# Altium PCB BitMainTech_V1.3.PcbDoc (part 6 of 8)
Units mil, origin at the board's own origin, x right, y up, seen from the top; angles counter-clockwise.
Board outline 9842.52 x 6082.68 mil, 4 copper layers (Top Layer, Mid-Layer 1, Mid-Layer 2, Bottom Layer); 987 components, 282 nets, 3694 pads, 3174 vias.
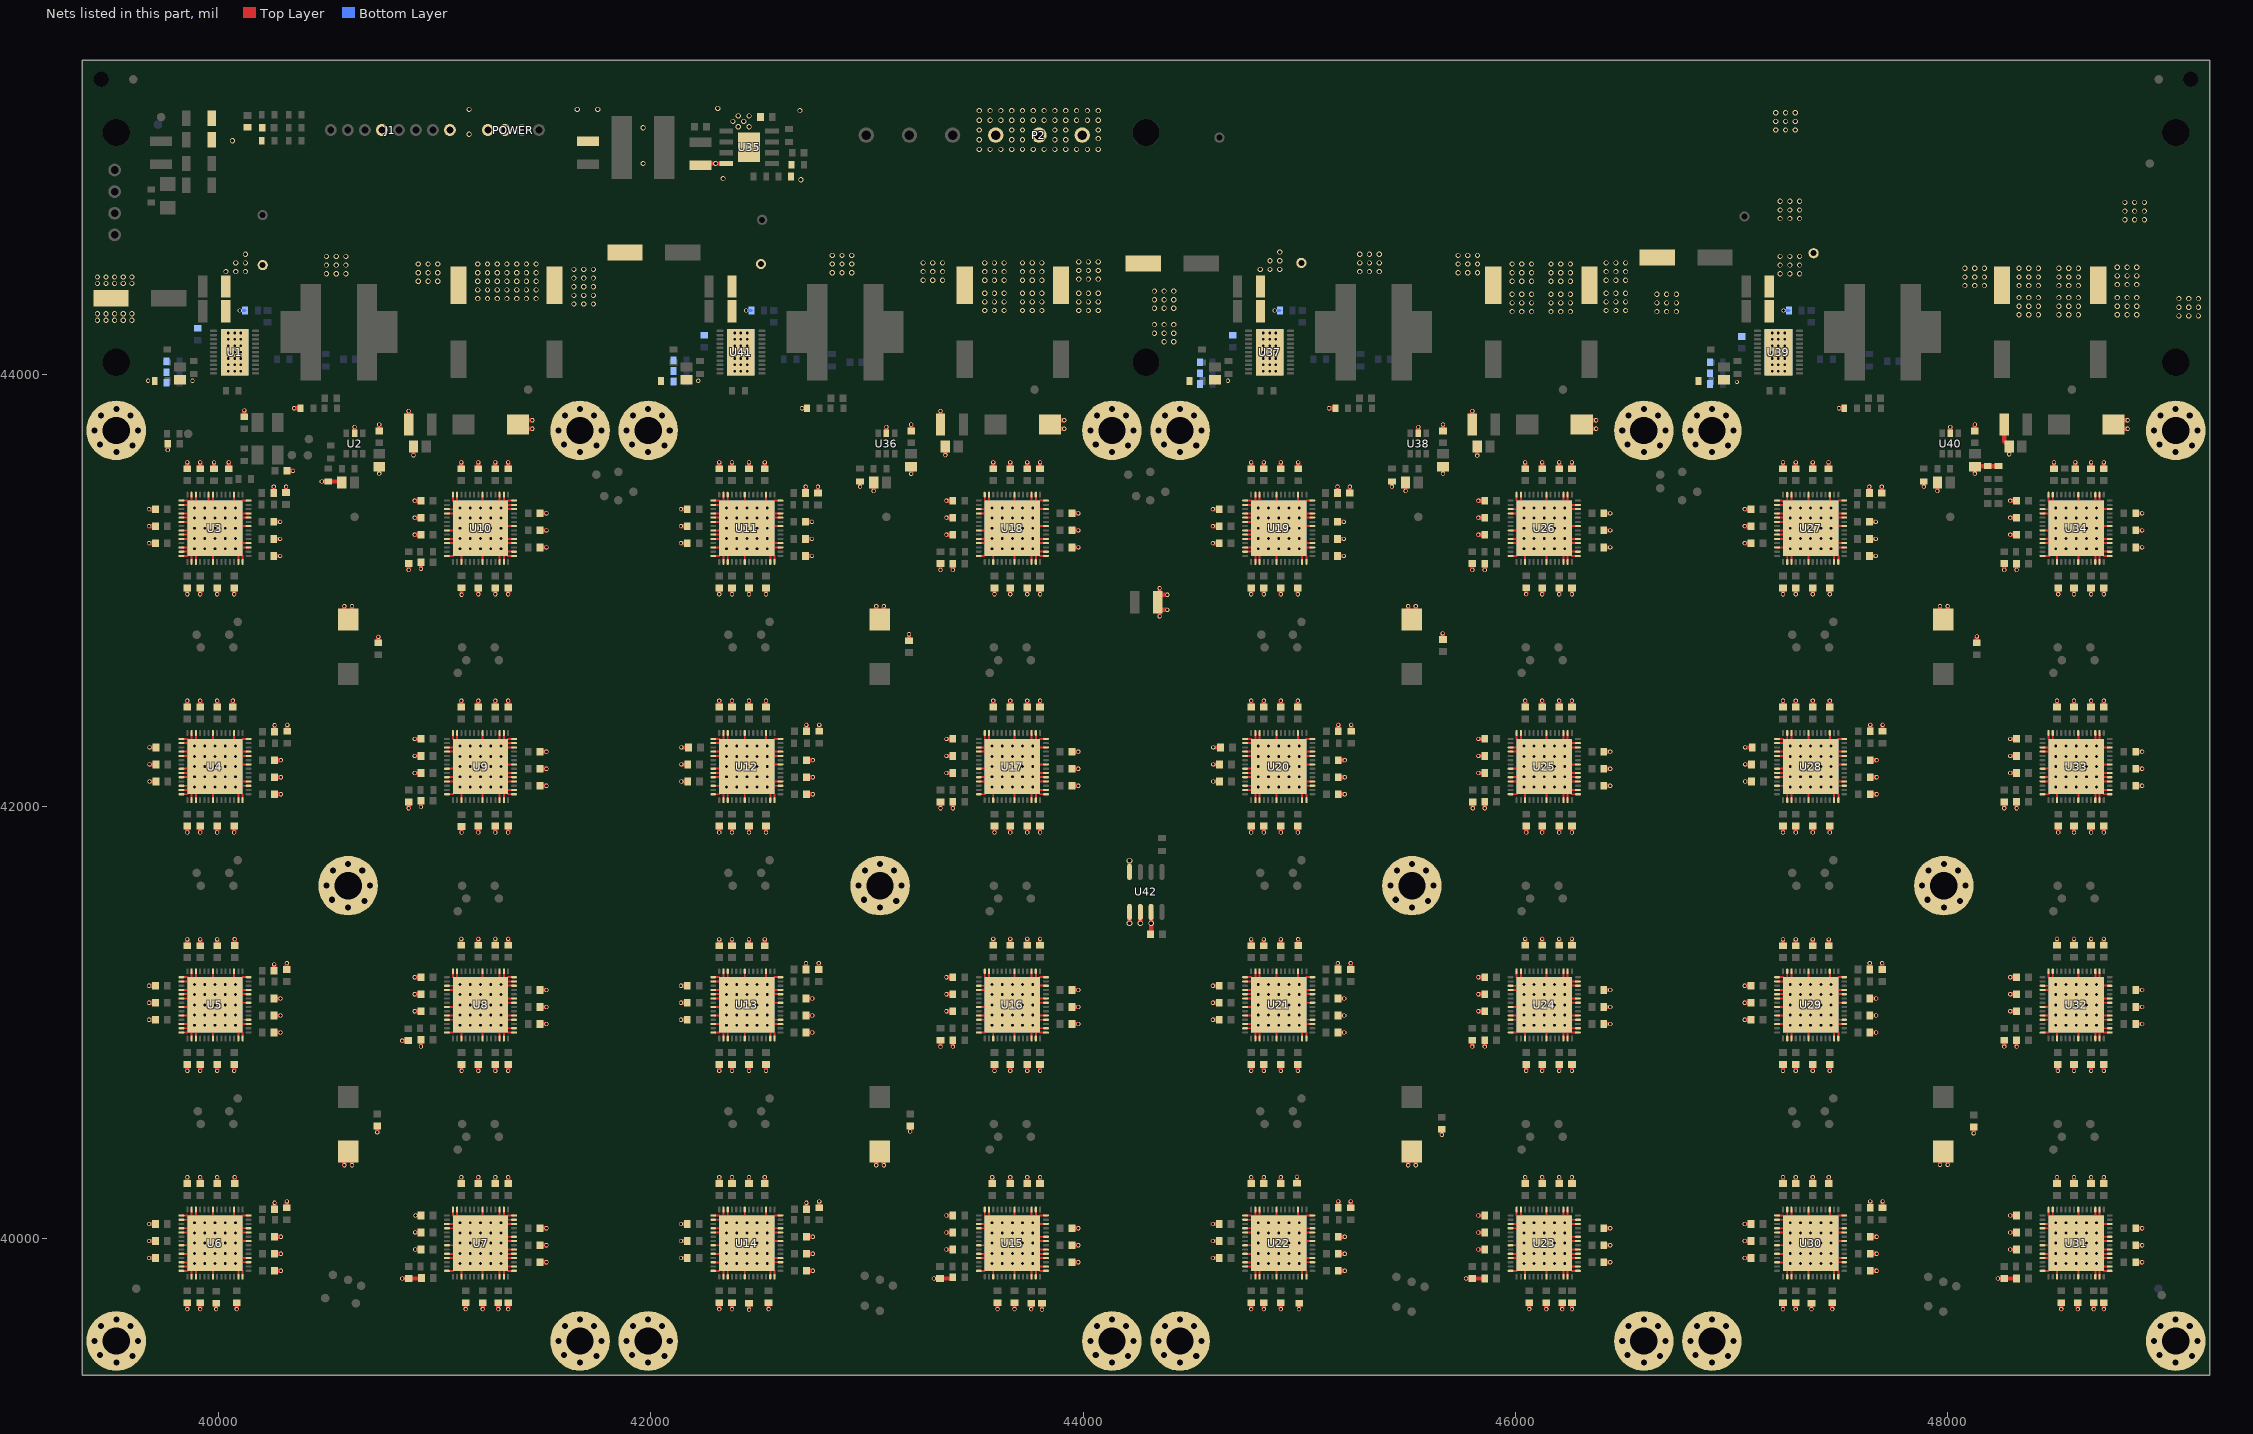
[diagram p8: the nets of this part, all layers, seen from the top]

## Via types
v1: diameter 19, hole 12, Top Layer to Bottom Layer, 1347 vias
v2: diameter 25.98, hole 12.99, Top Layer to Bottom Layer, 800 vias
v3: diameter 24, hole 16, Top Layer to Bottom Layer, 778 vias
v4: diameter 50, hole 28, Top Layer to Bottom Layer, 160 vias
v5: diameter 19.68, hole 11.81, Top Layer to Bottom Layer, 84 vias
v6: diameter 26, hole 18, Top Layer to Bottom Layer, 5 vias

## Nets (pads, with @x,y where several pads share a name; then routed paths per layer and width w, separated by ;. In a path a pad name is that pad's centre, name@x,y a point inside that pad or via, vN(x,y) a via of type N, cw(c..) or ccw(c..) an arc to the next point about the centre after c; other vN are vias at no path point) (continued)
GND: (continued)
  Top Layer w20: v1(39679.13,39911.42) C57.1@39708.66,39911.42 ; v1(39679.13,39990.16) C59.1@39708.66,39990.16 ; v1(39679.13,40068.9) C58.1@39708.66,40068.9 ; v1(39679.13,41013.78) C130.1@39708.66,41013.78 ; v1(39679.13,41092.52) C131.1@39708.66,41092.52 ; v1(39679.13,41171.26) C134.1@39708.66,41171.26 ; v1(39679.13,43218.5) C132.1@39708.66,43218.5 ; v1(39679.13,43297.24) C122.1@39708.66,43297.24 ; v1(39679.13,43375.98) C45.1@39708.66,43375.98 ; v1(39681.1,42116.14) C115.1@39710.63,42116.14 ; v1(39681.1,42194.88) C114.1@39710.63,42194.88 ; v1(39681.1,42273.62) C113.1@39710.63,42273.62 ; v1(39765.75,43649.61) C31.2@39765.75,43679.13 ; v1(39856.3,39675.2) C104.1@39856.3,39704.72 ; C103.1@39856.3,40255.91 v1(39856.3,40285.43) ; v1(39856.3,40777.56) C43.1@39856.3,40807.09 ; C35.1@39856.3,41356.3 v1(39856.3,41385.83) ; v1(39856.3,41879.92) C41.1@39856.3,41909.45 ; C33.1@39856.3,42460.63 v1(39856.3,42490.16) ; v1(39856.3,42982.28) C99.1@39856.3,43011.81 ; C106.1@39856.3,43562.99 v1(39856.3,43592.52) ; v1(39915.35,39675.2) C53.1@39915.35,39704.72 ; C124.1@39915.35,40255.91 v1(39915.35,40285.43) ; v1(39915.35,40777.56) C121.1@39915.35,40807.09 ; C52.1@39915.35,41356.3 v1(39915.35,41385.83) ; v1(39915.35,41879.92) C116.1@39915.35,41909.45 ; C110.1@39915.35,42460.63 v1(39915.35,42490.16) ; v1(39915.35,42982.28) C56.1@39915.35,43011.81 ; C47.1@39915.35,43562.99 v1(39915.35,43592.52) ; C50.1@39980,43562.56 v1(39980,43592.09) ; v1(39989.25,39675) C54.1@39989.25,39702.44 ; C125.1@39994.09,40255.91 v1(39994.09,40285.43) ; v1(39994.09,40777.56) C126.1@39994.09,40807.09 ; C51.1@39994.09,41356.3 v1(39994.09,41385.83) ; v1(39994.09,41879.92) C117.1@39994.09,41909.45 ; C111.1@39994.09,42460.63 v1(39994.09,42490.16) ; v1(39994.09,42982.28) C63.1@39994.09,43011.81 ; C133.1@40047.24,43562.99 v1(40047.24,43592.52) ; C112.1@40066.93,42460.63 v1(40066.93,42490.16) ; v1(40072.83,40777.56) C127.1@40072.83,40807.09 ; v1(40072.83,41879.92) C118.1@40072.83,41909.45 ; v1(40072.83,42982.28) C108.1@40072.83,43011.81 ; C123.1@40075,40255.9 v1(40075,40285.43) ; C48.1@40075,41357.56 v1(40075,41387.09) ; v1(40084.65,39675.2) C55.1@40084.65,39704.72 ; C30.2@40120.08,43803.15 v1(40120.08,43832.68) ; C105.1@40255.91,43159.45 v1(40285.43,43159.45) ; C49.1@40255.91,43238.19 v1(40285.43,43238.19) ; C109.1@40255.91,43316.93 v1(40285.43,43316.93) ; C22.1@40255.91,43450.79 v1(40255.91,43480.31) ; C40.1@40257.87,40954.72 v1(40287.4,40954.72) ; C128.1@40257.87,41033.46 v1(40287.4,41033.46) ; C129.1@40257.87,41112.2 v1(40287.4,41112.2) ; C26.1@40257.87,41240.16 v1(40257.87,41269.68) ; C107.1@40259.84,39852.36 v1(40289.37,39852.36) ; C135.1@40259.84,39931.1 v1(40289.37,39931.1) ; C136.1@40259.84,40009.84 v1(40289.37,40009.84) ; C28.1@40259.84,40137.8 v1(40259.84,40167.32) ; C39.1@40259.84,42057.09 v1(40289.37,42057.09) ; C119.1@40259.84,42135.83 v1(40289.37,42135.83) ; C120.1@40259.84,42214.57 v1(40289.37,42214.57) ; C24.1@40259.84,42346.46 v1(40259.84,42375.98) ; C21.2@40312.99,43452.76 v1(40312.99,43480) ; C27.2@40316.93,40143.7 v1(40316.93,40173.23) ; C92.2@40316.93,41246.06 v1(40316.93,41275.59) ; C29.2@40316.93,43553.15 v1(40345,43553.15) ; C90.2@40318.9,42348.43 v1(40318.9,42377.95) ; v1(40350.39,43842.52) R12.2@40379.92,43842.52 ; v1(40478.35,43503.94) R14.1@40507.87,43503.94 C16.1@40570.87,43503.94 ; v1(40582.68,40340.55) C18.2@40582.68,40405.51 ; C17.2@40582.68,42866.14 v1(40582.68,42927.17) ; v1(40618.11,40340.55) C18.2@40618.11,40401.57 ; C17.2@40618.11,42862.2 v1(40618.11,42927.17) ; U2.2@40629.92,43726.38 v1(40629.92,43755.91) ; v1(40735,40492.91) C19.1@40735,40522.44 ; C20.1@40740,42757.56 v1(40740,42785.12) ; v1(40744.09,43540) C15.1@40744.09,43572.83 ; C14.1@40744.09,43738.19 v1(40744.09,43767.72) ; v1(40850,40917.32) C25.2@40877.95,40917.32 ; v1(40850.39,39816.93) C94.2@40879.92,39816.93 C89.1@40938.98,39816.93 ; v1(40879.92,41992.13) C23.2@40879.92,42021.65 ; v1(40879.92,43094.49) C88.2@40879.92,43124.02 ; C8.1@40879.92,43767.72 v1(40879.92,43830) ; v1(40902.47,43625) C9.1@40902.47,43666 ; v1(40907.48,41053.15) C46.1@40937.01,41053.15 ; v1(40907.48,41131.89) C87.1@40937.01,41131.89 ; v1(40907.48,41210.63) C34.1@40937.01,41210.63 ; v1(40907.48,42155.51) C85.1@40937.01,42155.51 ; v1(40907.48,42234.25) C86.1@40937.01,42234.25 ; v1(40907.48,42312.99) C38.1@40937.01,42312.99 ; v1(40907.48,43257.87) C84.1@40937.01,43257.87 ; v1(40907.48,43336.61) C83.1@40937.01,43336.61 ; v1(40907.48,43415.35) C98.1@40937.01,43415.35 ; v1(40910,39950.79) C147.1@40937.01,39950.79 ; v1@40910.47,40029.53 C146.1@40937.01,40029.53 ; v1(40911.73,40108.27) C32.1@40937.01,40108.27 ; v1(40937.01,40890) C91.1@40937.01,40921.26 ; v1(40937.01,41998.03) C93.1@40937.01,42027.56 ; v1(40937.01,43100.39) C95.1@40937.01,43129.92 ; C142.1@41124.02,40255.91 v1(41124.02,40285.43) ; C62.1@41124.02,41358.27 v1(41124.02,41387.8) ; C69.1@41124.02,42460.63 v1(41124.02,42490.16) ; C82.1@41124.02,43562.99 v1(41124.02,43592.52) ; v1(41125,40777.91) C148.1@41125,40807.44 ; v1(41125,41880) C64.1@41125,41909.53 ; v1(41125,42980) C73.1@41125,43009.53 ; v1(41143.7,39675.2) C137.1@41143.7,39704.72 ; C141.1@41202.76,40255.91 v1(41202.76,40285.43) ; v1(41202.76,40777.56) C149.1@41202.76,40807.09 ; C61.1@41202.76,41358.27 v1(41202.76,41387.8) ; v1(41202.76,41879.92) C65.1@41202.76,41909.45 ; C68.1@41202.76,42460.63 v1(41202.76,42490.16) ; v1(41202.76,42982.28) C74.1@41202.76,43011.81 ; C81.1@41202.76,43562.99 v1(41202.76,43592.52) ; v1(41222.44,39675.2) C138.1@41222.44,39704.72 ; C140.1@41281.5,40255.91 v1(41281.5,40285.43) ; v1(41281.5,40777.56) C150.1@41281.5,40807.09 ; C60.1@41281.5,41358.27 v1(41281.5,41387.8) ; v1(41281.5,41879.92) C66.1@41281.5,41909.45 ; C67.1@41281.5,42460.63 v1(41281.5,42490.16) ; v1(41281.5,42982.28) C76.1@41281.5,43011.81 ; C80.1@41281.5,43562.99 v1(41281.5,43592.52) ; v1(41295.28,39675.2) C139.1@41295.28,39704.72 ; v1(41340.55,39675.2) C36.1@41340.55,39704.72 ; C102.1@41340.55,40255.91 v1(41340.55,40285.43) ; v1(41340.55,40777.56) C37.1@41340.55,40807.09 ; C101.1@41340.55,41358.27 v1(41340.55,41387.8) ; v1(41340.55,41879.92) C96.1@41340.55,41909.45 ; C100.1@41340.55,42460.63 v1(41340.55,42490.16) ; v1(41340.55,42982.28) C97.1@41340.55,43011.81 ; C42.1@41340.55,43562.99 v1(41340.55,43592.52) ; C4.2@41381.89,43748.03 v1(41452.76,43748.03) ; C4.2@41385.83,43787.4 v1(41452.76,43787.4) ; C145.1@41488.19,39891.73 v1(41517.72,39891.73) ; C144.1@41488.19,39970.47 v1(41517.72,39970.47) ; C143.1@41488.19,40049.21 v1(41517.72,40049.21) ; C151.1@41488.19,40994.09 v1(41517.72,40994.09) ; C75.1@41488.19,41072.83 v1(41517.72,41072.83) ; C44.1@41488.19,41151.57 v1(41517.72,41151.57) ; C70.1@41488.19,42096.46 v1(41517.72,42096.46) ; C71.1@41488.19,42175.2 v1(41517.72,42175.2) ; C72.1@41488.19,42253.94 v1(41517.72,42253.94) ; C77.1@41488.19,43198.82 v1(41517.72,43198.82) ; C78.1@41488.19,43277.56 v1(41517.72,43277.56) ; C79.1@41488.19,43356.3 v1(41517.72,43356.3) ; v1(42139.76,39911.42) C189.1@42169.29,39911.42 ; v1(42139.76,39990.16) C191.1@42169.29,39990.16 ; v1(42139.76,40068.9) C190.1@42169.29,40068.9 ; v1(42139.76,41013.78) C262.1@42169.29,41013.78 ; v1(42139.76,41092.52) C263.1@42169.29,41092.52 ; v1(42139.76,41171.26) C266.1@42169.29,41171.26 ; v1(42139.76,43218.5) C264.1@42169.29,43218.5 ; v1(42139.76,43297.24) C254.1@42169.29,43297.24 ; v1(42139.76,43375.98) C177.1@42169.29,43375.98 ; v1(42141.73,42116.14) C247.1@42171.26,42116.14 ; v1(42141.73,42194.88) C246.1@42171.26,42194.88 ; v1(42141.73,42273.62) C245.1@42171.26,42273.62 ; C548.1@42242.09,44975 U35.4@42348.7,44975 ; v1(42316.93,39675.2) C236.1@42316.93,39704.72 ; C235.1@42316.93,40255.91 v1(42316.93,40285.43) ; v1(42316.93,40777.56) C175.1@42316.93,40807.09 ; C167.1@42316.93,41356.3 v1(42316.93,41385.83) ; v1(42316.93,41879.92) C173.1@42316.93,41909.45 ; C165.1@42316.93,42460.63 v1(42316.93,42490.16) ; v1(42316.93,42982.28) C231.1@42316.93,43011.81 ; C238.1@42316.93,43562.99 v1(42316.93,43592.52) ; v1(42375.98,39675.2) C185.1@42375.98,39704.72 ; C256.1@42375.98,40255.91 v1(42375.98,40285.43) ; v1(42375.98,40777.56) C253.1@42375.98,40807.09 ; C184.1@42375.98,41356.3 v1(42375.98,41385.83) ; v1(42375.98,41879.92) C248.1@42375.98,41909.45 ; C242.1@42375.98,42460.63 v1(42375.98,42490.16) ; v1(42375.98,42982.28) C188.1@42375.98,43011.81 ; C179.1@42375.98,43562.99 v1(42375.98,43592.52) ; C257.1@42454.72,40255.91 v1(42454.72,40285.43) ; v1(42454.72,40777.56) C258.1@42454.72,40807.09 ; C183.1@42454.72,41356.3 v1(42454.72,41385.83) ; v1(42454.72,41879.92) C249.1@42454.72,41909.45 ; C243.1@42454.72,42460.63 v1(42454.72,42490.16) ; v1(42454.72,42982.28) C195.1@42454.72,43011.81 ; C182.1@42454.72,43562.99 v1(42454.72,43592.52) ; v1(42455,39672.91) C186.1@42455,39702.44 ; C255.1@42527.56,40255.91 v1(42527.56,40285.43) ; C180.1@42527.56,41356.3 v1(42527.56,41385.83) ; C265.1@42527.56,43562.99 v1(42527.56,43592.52) ; v1(42533.46,40777.56) C259.1@42533.46,40807.09 ; v1(42533.46,41879.92) C250.1@42533.46,41909.45 ; C244.1@42533.46,42460.63 v1(42533.46,42490.16) ; v1(42533.46,42982.28) C240.1@42533.46,43011.81 ; v1(42545.28,39675.2) C187.1@42545.28,39704.72 ; v1(42700,43842.52) R33.2@42722.44,43842.52 ; C237.1@42716.54,43159.45 v1(42746.06,43159.45) ; C181.1@42716.54,43238.19 v1(42746.06,43238.19) ; C241.1@42716.54,43316.93 v1(42746.06,43316.93) ; C157.1@42716.54,43450.79 v1(42716.54,43480.31) ; C172.1@42718.5,40954.72 v1(42748.03,40954.72) ; C260.1@42718.5,41033.46 v1(42748.03,41033.46) ; C261.1@42718.5,41112.2 v1(42748.03,41112.2) ; C161.1@42718.5,41246.06 v1(42718.5,41275.59) ; C239.1@42720.47,39852.36 v1(42750,39852.36) ; C267.1@42720.47,39931.1 v1(42750,39931.1) ; C268.1@42720.47,40009.84 v1(42750,40009.84) ; C163.1@42720.47,40137.8 v1(42720.47,40167.32) ; C171.1@42720.47,42057.09 v1(42750,42057.09) ; C251.1@42720.47,42135.83 v1(42750,42135.83) ; C252.1@42720.47,42214.57 v1(42750,42214.57) ; C159.1@42720.47,42348.43 v1(42720.47,42377.95) ; C156.2@42773.62,43450.79 v1(42773.62,43480.32) ; C224.2@42777.56,41246.06 v1(42777.56,41275.59) ; C162.2@42779.53,40143.7 v1(42779.53,40173.23) ; C222.2@42779.53,42348.43 v1(42779.53,42377.95) ; v1(42968.5,43480) R35.1@42968.5,43503.94 ; v1(43031.5,43460) C563.1@43031.5,43500 ; v1(43043.31,40340.55) C153.2@43043.31,40405.51 ; C152.2@43043.31,42866.14 v1(43043.31,42927.17) ; v1(43078.74,40340.55) C153.2@43078.74,40401.57 ; C152.2@43078.74,42862.2 v1(43078.74,42927.17) ; U36.2@43090.55,43726.38 v1(43090.55,43755.91) ; C155.1@43195,42767.56 v1(43195,42797.09) ; v1(43200,40496.85) C154.1@43200,40522.44 ; v1(43204.72,43539.37) C562.1@43204.72,43572.83 ; C561.1@43204.72,43738.19 v1(43204.72,43767.72) ; v1(43310,39816.93) C226.2@43338.58,39816.93 43391.73,39816.93 C221.1@43397.64,39822.83 ; v1(43340.55,40889.76) C160.2@43340.55,40919.29 ; v1(43340.55,41992.13) C158.2@43340.55,42021.65 ; v1(43340.55,43094.49) C220.2@43340.55,43124.02 ; C555.1@43340.55,43767.72 v1(43340.55,43830) ; v1(43363.1,43625.98) C556.1@43363.1,43666 ; v1(43368.11,39950.79) C279.1@43397.64,39950.79 ; v1(43368.11,40029.53) C278.1@43397.64,40029.53 ; v1(43368.11,40108.27) C164.1@43397.64,40108.27 ; v1(43368.11,41053.15) C178.1@43397.64,41053.15 ; v1(43368.11,41131.89) C219.1@43397.64,41131.89 ; v1(43368.11,41210.63) C166.1@43397.64,41210.63 ; v1(43368.11,42155.51) C217.1@43397.64,42155.51 ; v1(43368.11,42234.25) C218.1@43397.64,42234.25 ; v1(43368.11,42312.99) C170.1@43397.64,42312.99 ; v1(43368.11,43257.87) C216.1@43397.64,43257.87 ; v1(43368.11,43336.61) C215.1@43397.64,43336.61 ; v1(43368.11,43415.35) C230.1@43397.64,43415.35 ; v1(43397.64,40889.76) C223.1@43397.64,40919.29 ; v1(43397.64,41992.13) C225.1@43397.64,42021.65 ; v1(43397.64,43094.49) C227.1@43397.64,43124.02 ; C274.1@43580,40257.56 v1(43580,40285) ; C194.1@43584.65,41358.27 v1(43584.65,41387.8) ; C201.1@43584.65,42460.63 v1(43584.65,42490.16) ; C214.1@43584.65,43562.99 v1(43584.65,43592.52) ; v1(43590.55,40777.56) C280.1@43590.55,40807.09 ; v1(43590.55,41879.92) C196.1@43590.55,41909.45 ; v1(43590.55,42982.28) C205.1@43590.55,43011.81 ; v1(43604.33,39675.2) C269.1@43604.33,39704.72 ; C273.1@43663.39,40255.91 v1(43663.39,40285.43) ; v1(43663.39,40777.56) C281.1@43663.39,40807.09 ; C193.1@43663.39,41358.27 v1(43663.39,41387.8) ; v1(43663.39,41879.92) C197.1@43663.39,41909.45 ; C200.1@43663.39,42460.63 v1(43663.39,42490.16) ; v1(43663.39,42982.28) C206.1@43663.39,43011.81 ; C213.1@43663.39,43562.99 v1(43663.39,43592.52) ; v1(43683.07,39675.2) C270.1@43683.07,39704.72 ; C272.1@43742.13,40255.91 v1(43742.13,40285.43) ; v1(43742.13,40777.56) C282.1@43742.13,40807.09 ; C192.1@43742.13,41358.27 v1(43742.13,41387.8) ; v1(43742.13,41879.92) C198.1@43742.13,41909.45 ; C199.1@43742.13,42460.63 v1(43742.13,42490.16) ; v1(43742.13,42982.28) C208.1@43742.13,43011.81 ; C212.1@43742.13,43562.99 v1(43742.13,43592.52) ; v1(43760,39675) C271.1@43760,39704.53 ; C234.1@43801.18,40255.91 v1(43801.18,40285.43) ; v1(43801.18,40777.56) C169.1@43801.18,40807.09 ; C233.1@43801.18,41358.27 v1(43801.18,41387.8) ; v1(43801.18,41879.92) C228.1@43801.18,41909.45 ; C232.1@43801.18,42460.63 v1(43801.18,42490.16) ; v1(43801.18,42982.28) C229.1@43801.18,43011.81 ; C174.1@43801.18,43562.99 v1(43801.18,43592.52) ; v1(43810,39672.91) C168.1@43810,39702.44 ; C599.2@43842.52,43748.03 v1(43913.39,43748.03) ; C599.2@43846.46,43787.4 v1(43913.39,43787.4) ; C277.1@43948.82,39891.73 v1(43978.35,39891.73) ; C276.1@43948.82,39970.47 v1(43978.35,39970.47) ; C275.1@43948.82,40049.21 v1(43978.35,40049.21) ; C283.1@43948.82,40994.09 v1(43978.35,40994.09) ; C207.1@43948.82,41072.83 v1(43978.35,41072.83) ; C176.1@43948.82,41151.57 v1(43978.35,41151.57) ; C202.1@43948.82,42096.46 v1(43978.35,42096.46) ; C203.1@43948.82,42175.2 v1(43978.35,42175.2) ; C204.1@43948.82,42253.94 v1(43978.35,42253.94) ; C209.1@43948.82,43198.82 v1(43978.35,43198.82) ; C210.1@43948.82,43277.56 v1(43978.35,43277.56) ; C211.1@43948.82,43356.3 v1(43978.35,43356.3) ; v6(44215,41460.2) U42.5@44215,41512.48 ; U42.4@44215,41697.52 v6(44215,41749.8) ; v6(44265,41460.2) U42.6@44265,41512.48 ; C601.2@44315,41410 U42.7@44315,41512.48 ; v1(44354.17,42880) 44354.17,42910 v1(44390,42910) ; v1(44354.17,43010) 44354.17,42980 v1(44390,42980) ; v1(44600.39,39911.42) C321.1@44629.92,39911.42 ; v1(44600.39,39990.16) C323.1@44629.92,39990.16 ; v1(44600.39,40068.9) C322.1@44629.92,40068.9 ; v1(44600.39,41013.78) C394.1@44629.92,41013.78 ; v1(44600.39,41092.52) C395.1@44629.92,41092.52 ; v1(44600.39,41171.26) C398.1@44629.92,41171.26 ; v1(44600.39,43218.5) C396.1@44629.92,43218.5 ; v1(44600.39,43297.24) C386.1@44629.92,43297.24 ; v1(44600.39,43375.98) C309.1@44629.92,43375.98 ; v1(44602.36,42116.14) C379.1@44631.89,42116.14 ; v1(44602.36,42194.88) C378.1@44631.89,42194.88 ; v1(44602.36,42273.62) C377.1@44631.89,42273.62 ; v1(44777.56,39675.2) C368.1@44777.56,39704.72 ; C367.1@44777.56,40255.91 v1(44777.56,40285.43) ; v1(44777.56,40777.56) C307.1@44777.56,40807.09 ; C299.1@44777.56,41356.3 v1(44777.56,41385.83) ; v1(44777.56,41879.92) C305.1@44777.56,41909.45 ; C297.1@44777.56,42460.63 v1(44777.56,42490.16) ; v1(44777.56,42982.28) C363.1@44777.56,43011.81 ; C370.1@44777.56,43562.99 v1(44777.56,43592.52) ; v1(44836.61,39675.2) C317.1@44836.61,39704.72 ; C388.1@44836.61,40255.91 v1(44836.61,40285.43) ; v1(44836.61,40777.56) C385.1@44836.61,40807.09 ; C316.1@44836.61,41356.3 v1(44836.61,41385.83) ; v1(44836.61,41879.92) C380.1@44836.61,41909.45 ; C374.1@44836.61,42460.63 v1(44836.61,42490.16) ; v1(44836.61,42982.28) C320.1@44836.61,43011.81 ; C311.1@44836.61,43562.99 v1(44836.61,43592.52) ; v1(44915.34,39675.2) C318.1@44915.34,39704.72 ; C389.1@44915.35,40255.91 v1(44915.35,40285.43) ; v1(44915.35,40777.56) C390.1@44915.35,40807.09 ; C315.1@44915.35,41356.3 v1(44915.35,41385.83) ; v1(44915.35,41879.92) C381.1@44915.35,41909.45 ; C375.1@44915.35,42460.63 v1(44915.35,42490.16) ; v1(44915.35,42982.28) C327.1@44915.35,43011.81 ; C314.1@44915.35,43562.99 v1(44915.35,43592.52) ; C387.1@44990,40257.56 v1(44990,40287.09) ; v1(44994.09,40777.56) C391.1@44994.09,40807.09 ; v1(44994.09,41879.92) C382.1@44994.09,41909.45 ; C376.1@44994.09,42460.63 v1(44994.09,42490.16) ; v1(44994.09,42982.28) C372.1@44994.09,43011.81 ; C312.1@44995,41357.56 v1(44995,41387.09) ; C397.1@44995,43562.56 v1(44995,43592.09) ; v1(44999.08,39675.2) C319.1@44999.08,39704.72 ; v1(45137.8,43842.52) R47.2@45167.32,43842.52 ; C369.1@45177.17,43159.45 v1(45206.69,43159.45) ; C313.1@45177.17,43238.19 v1(45206.69,43238.19) ; C373.1@45177.17,43316.93 v1(45206.69,43316.93) ; C289.1@45177.15,43450.79 v1(45177.15,43480.31) ; C293.1@45179.12,41246.06 v1(45179.12,41275.59) ; C304.1@45179.13,40954.72 v1(45208.66,40954.72) ; C392.1@45179.13,41033.46 v1(45208.66,41033.46) ; C393.1@45179.13,41112.2 v1(45208.66,41112.2) ; C371.1@45181.1,39852.36 v1(45210.63,39852.36) ; C399.1@45181.1,39931.1 v1(45210.63,39931.1) ; C400.1@45181.1,40009.84 v1(45210.63,40009.84) ; C295.1@45181.08,40143.7 v1(45181.08,40173.23) ; C303.1@45181.1,42057.09 v1(45210.63,42057.09) ; C383.1@45181.1,42135.83 v1(45210.63,42135.83) ; C384.1@45181.1,42214.57 v1(45210.63,42214.57) ; C291.1@45181.08,42348.43 v1(45181.08,42377.95) ; C288.2@45234.23,43450.79 v1(45234.23,43480.31) ; C294.2@45238.17,40143.7 v1(45238.17,40173.23) ; C356.2@45238.17,41246.06 v1(45238.17,41275.59) ; C354.2@45240.14,42348.43 v1(45240.14,42377.95) ; v1(45429.13,43480) R49.1@45429.13,43503.94 ; v1(45492.13,43460) C579.1@45492.13,43500 ; v1(45503.94,40340.55) C285.2@45503.94,40405.51 ; C284.2@45503.94,42866.14 v1(45503.94,42927.17) ; v1(45539.37,40340.55) C285.2@45539.37,40401.57 ; C284.2@45539.37,42862.2 v1(45539.37,42927.17) ; U38.2@45551.18,43726.38 v1(45551.18,43755.91) ; v1(45660,40481.85) C286.1@45660,40507.44 ; C287.1@45663.48,42771.56 v1(45663.48,42801.09) ; v1(45665.35,43540) C578.1@45665.35,43572.83 ; C577.1@45665.35,43738.19 v1(45665.35,43767.72) ; v1(45771.64,39816.93) C358.2@45801.16,39816.93 C353.1@45858.25,39816.93 ; v1(45801.16,40889.76) C292.2@45801.16,40919.29 ; v1(45801.16,43094.49) C352.2@45801.16,43124.02 ; C571.1@45801.18,43767.72 v1(45801.18,43830) ; v1(45803.13,41992.13) C290.2@45803.13,42021.65 ; v1(45823.73,43623.73) C572.1@45823.73,43666 ; v1(45828.74,39950.79) C411.1@45858.27,39950.79 ; v1(45828.74,40029.53) C410.1@45858.27,40029.53 ; v1(45828.74,40108.27) C296.1@45858.27,40108.27 ; v1(45828.74,41053.15) C310.1@45858.27,41053.15 ; v1(45828.74,41131.89) C351.1@45858.27,41131.89 ; v1(45828.74,41210.63) C298.1@45858.27,41210.63 ; v1(45828.74,42155.51) C349.1@45858.27,42155.51 ; v1(45828.74,42234.25) C350.1@45858.27,42234.25 ; v1(45828.74,42312.99) C302.1@45858.27,42312.99 ; v1(45828.74,43257.87) C348.1@45858.27,43257.87 ; v1(45828.74,43336.61) C347.1@45858.27,43336.61 ; v1(45828.74,43415.35) C362.1@45858.27,43415.35 ; v1(45858.25,40889.76) C355.1@45858.25,40919.29 ; v1(45858.25,41992.13) C357.1@45858.25,42021.65 ; v1(45858.25,43094.49) C359.1@45858.25,43124.02 ; C406.1@46045.28,40255.91 v1(46045.28,40285.43) ; C326.1@46045.28,41358.27 v1(46045.28,41387.8) ; C333.1@46045.28,42460.63 v1(46045.28,42490.16) ; C346.1@46045.28,43562.99 v1(46045.28,43592.52) ; v1(46050,40777.91) C412.1@46050,40807.44 ; v1(46050,42982.91) C337.1@46050,43012.44 ; v1(46051.16,41879.92) C328.1@46051.16,41909.45 ; v1(46064.96,39675.2) C401.1@46064.96,39704.72 ; C405.1@46124.02,40255.91 v1(46124.02,40285.43) ; v1(46124.02,40777.56) C413.1@46124.02,40807.09 ; C325.1@46124.02,41358.27 v1(46124.02,41387.8) ; v1(46124.02,41879.92) C329.1@46124.02,41909.45 ; C332.1@46124.02,42460.63 v1(46124.02,42490.16) ; v1(46124.02,42982.28) C338.1@46124.02,43011.81 ; C345.1@46124.02,43562.99 v1(46124.02,43592.52) ; v1(46143.7,39675.2) C402.1@46143.7,39704.72 ; C404.1@46202.76,40255.91 v1(46202.76,40285.43) ; v1(46202.76,40777.56) C414.1@46202.76,40807.09 ; C324.1@46202.76,41358.27 v1(46202.76,41387.8) ; v1(46202.76,41879.92) C330.1@46202.76,41909.45 ; C331.1@46202.76,42460.63 v1(46202.76,42490.16) ; v1(46202.76,42982.28) C340.1@46202.76,43011.81 ; C344.1@46202.76,43562.99 v1(46202.76,43592.52) ; v1(46216.52,39675.2) C403.1@46216.52,39704.72 ; v1(46261.81,39675.2) C300.1@46261.81,39704.72 ; C366.1@46261.81,40255.91 v1(46261.81,40285.43) ; v1(46261.81,40777.56) C301.1@46261.81,40807.09 ; C365.1@46261.81,41358.27 v1(46261.81,41387.8) ; v1(46261.81,41879.92) C360.1@46261.81,41909.45 ; C364.1@46261.81,42460.63 v1(46261.81,42490.16) ; v1(46261.81,42982.28) C361.1@46261.81,43011.81 ; C306.1@46261.81,43562.99 v1(46261.81,43592.52) ; C567.2@46303.15,43748.03 v1(46374.02,43748.03) ; C567.2@46316.93,43787.4 v1(46374.02,43787.4) ; C409.1@46409.45,39891.73 v1(46438.98,39891.73) ; C408.1@46409.45,39970.47 v1(46438.98,39970.47) ; C407.1@46409.45,40049.21 v1(46438.98,40049.21) ; C415.1@46409.45,40994.09 v1(46438.98,40994.09) ; C339.1@46409.45,41072.83 v1(46438.98,41072.83) ; C308.1@46409.45,41151.57 v1(46438.98,41151.57) ; C334.1@46409.45,42096.46 v1(46438.98,42096.46) ; C335.1@46409.45,42175.2 v1(46438.98,42175.2) ; C336.1@46409.45,42253.94 v1(46438.98,42253.94) ; C341.1@46409.45,43198.82 v1(46438.98,43198.82) ; C342.1@46409.45,43277.56 v1(46438.98,43277.56) ; C343.1@46409.45,43356.3 v1(46438.98,43356.3) ; v1(47061.02,39911.42) C453.1@47090.55,39911.42 ; v1(47061.02,39990.16) C455.1@47090.55,39990.16 ; v1(47061.02,40068.9) C454.1@47090.55,40068.9 ; v1(47061.02,41013.78) C526.1@47090.55,41013.78 ; v1(47061.02,41092.52) C527.1@47090.55,41092.52 ; v1(47061.02,41171.26) C530.1@47090.55,41171.26 ; v1(47061.02,43218.5) C528.1@47090.55,43218.5 ; v1(47061.02,43297.24) C518.1@47090.55,43297.24 ; v1(47061.02,43375.98) C441.1@47090.55,43375.98 ; v1(47062.99,42116.14) C511.1@47092.52,42116.14 ; v1(47062.99,42194.88) C510.1@47092.52,42194.88 ; v1(47062.99,42273.62) C509.1@47092.52,42273.62 ; v1(47238.19,39675.2) C500.1@47238.19,39704.72 ; C499.1@47238.19,40255.91 v1(47238.19,40285.43) ; v1(47238.19,40777.56) C439.1@47238.19,40807.09 ; C431.1@47238.19,41356.3 v1(47238.19,41385.83) ; v1(47238.19,41879.92) C437.1@47238.19,41909.45 ; C429.1@47238.19,42460.63 v1(47238.19,42490.16) ; v1(47238.19,42982.28) C495.1@47238.19,43011.81 ; C502.1@47238.19,43562.99 v1(47238.19,43592.52) ; v1(47297.24,39675.2) C449.1@47297.24,39704.72 ; C520.1@47297.24,40255.91 v1(47297.24,40285.43) ; v1(47297.24,40777.56) C517.1@47297.24,40807.09 ; C448.1@47297.24,41356.3 v1(47297.24,41385.83) ; v1(47297.24,41879.92) C512.1@47297.24,41909.45 ; C506.1@47297.24,42460.63 v1(47297.24,42490.16) ; v1(47297.24,42982.28) C452.1@47297.24,43011.81 ; C443.1@47297.24,43562.99 v1(47297.24,43592.52) ; v1(47370,39675) C450.1@47370,39704.53 ; C521.1@47375.98,40255.91 v1(47375.98,40285.43) ; v1(47375.98,40777.56) C522.1@47375.98,40807.09 ; C447.1@47375.98,41356.3 v1(47375.98,41385.83) ; v1(47375.98,41879.92) C513.1@47375.98,41909.45 ; C507.1@47375.98,42460.63 v1(47375.98,42490.16) ; v1(47375.98,42982.28) C459.1@47375.98,43011.81 ; C446.1@47375.98,43562.99 v1(47375.98,43592.52) ; C529.1@47448.82,43562.99 v1(47448.82,43592.52) ; C519.1@47450,40255.9 v1(47450,40285.43) ; C444.1@47450,41355.9 v1(47450,41385.43) ; v1(47454.72,40777.56) C523.1@47454.72,40807.09 ; v1(47454.72,41879.92) C514.1@47454.72,41909.45 ; C508.1@47454.72,42460.63 v1(47454.72,42490.16) ; v1(47454.72,42982.28) C504.1@47454.72,43011.81 ; v1(47466.54,39675.2) C451.1@47466.54,39704.72 ; v1(47497.52,43842.52) R61.2@47521.65,43842.52 ; C501.1@47637.8,43159.45 v1(47667.32,43159.45) ; C445.1@47637.8,43238.19 v1(47667.32,43238.19) ; C505.1@47637.8,43316.93 v1(47667.32,43316.93) ; C421.1@47637.8,43450.79 v1(47637.8,43480.31) ; C436.1@47639.76,40954.72 v1(47669.29,40954.72) ; C524.1@47639.76,41033.46 v1(47669.29,41033.46) ; C525.1@47639.76,41112.2 v1(47669.29,41112.2) ; C425.1@47639.76,41246.06 v1(47639.76,41275.59) ; C503.1@47641.73,39852.36 v1(47671.26,39852.36) ; C531.1@47641.73,39931.1 v1(47671.26,39931.1) ; C532.1@47641.73,40009.84 v1(47671.26,40009.84) ; C427.1@47641.73,40143.7 v1(47641.73,40173.23) ; C435.1@47641.73,42057.09 v1(47671.26,42057.09) ; C515.1@47641.73,42135.83 v1(47671.26,42135.83) ; C516.1@47641.73,42214.57 v1(47671.26,42214.57) ; C423.1@47641.73,42348.43 v1(47641.73,42377.95) ; C420.2@47694.88,43450.79 v1(47694.88,43480.31) ; C488.2@47696.85,41246.06 v1(47696.85,41275.59) ; C426.2@47698.82,40143.7 v1(47698.82,40173.23) ; C486.2@47698.82,42348.43 v1(47698.82,42377.95) ; R63.1@47889.76,43503.94 v1(47890,43480) ; v1(47952.76,43460) C595.1@47952.76,43500 ; v1(47964.57,40342.52) C417.2@47964.57,40407.48 ; C416.2@47964.57,42866.14 v1(47964.57,42927.17) ; v1(48000,40342.52) C417.2@48000,40403.54 ; C416.2@48000,42862.2 v1(48000,42927.17) ; U40.2@48011.81,43726.38 v1(48011.81,43755.91) ; v1(48120,40487.91) C418.1@48120,40517.44 ; v1(48125.98,43540) C594.1@48125.98,43572.83 ; C593.1@48125.98,43738.19 v1(48125.98,43767.72) ; C594.1@48127.68,43574.53 R20.1@48185,43574.53 R19.1@48235,43574.53 ; C419.1@48135,42757.56 v1(48135,42787.09) ; v1(48232.28,39816.93) C490.2@48261.81,39816.93 C485.1@48318.9,39816.93 ; v1(48261.81,40889.76) C424.2@48261.81,40919.29 ; v1(48261.81,41992.13) C422.2@48261.81,42021.65 ; v1(48261.81,43094.49) C484.2@48261.81,43124.02 ; C587.1@48261.81,43767.72 48261.81,43688.55 C588.1@48284.36,43666 v1(48284.36,43630) ; v1(48289.37,39950.79) C543.1@48318.9,39950.79 ; v1(48289.37,40029.53) C542.1@48318.9,40029.53 ; v1(48289.37,40108.27) C428.1@48318.9,40108.27 ; v1(48289.37,41053.15) C442.1@48318.9,41053.15 ; v1(48289.37,41131.89) C483.1@48318.9,41131.89 ; v1(48289.37,41210.63) C430.1@48318.9,41210.63 ; v1(48289.37,42155.51) C481.1@48318.9,42155.51 ; v1(48289.37,42234.25) C482.1@48318.9,42234.25 ; v1(48289.37,42312.99) C434.1@48318.9,42312.99 ; v1(48289.37,43257.87) C480.1@48318.9,43257.87 ; v1(48289.37,43336.61) C479.1@48318.9,43336.61 ; v1(48289.37,43415.35) C494.1@48318.9,43415.35 ; v1(48318.9,40889.76) C487.1@48318.9,40919.29 ; v1(48318.9,41992.13) C489.1@48318.9,42021.65 ; v1(48318.9,43094.49) C491.1@48318.9,43124.02 ; C478.1@48492.13,43562.99 v1(48492.13,43592.52) ; C538.1@48505.91,40255.91 v1(48505.91,40285.43) ; C458.1@48505.91,41358.27 v1(48505.91,41387.8) ; C465.1@48505.91,42460.63 v1(48505.91,42490.16) ; v1(48510,40777.91) C544.1@48510,40807.44 ; v1(48511.81,41879.92) C460.1@48511.81,41909.45 ; v1(48511.81,42982.28) C469.1@48511.81,43011.81 ; v1(48525.59,39675.2) C533.1@48525.59,39704.72 ; C537.1@48584.65,40255.91 v1(48584.65,40285.43) ; v1(48584.65,40777.56) C545.1@48584.65,40807.09 ; C457.1@48584.65,41358.27 v1(48584.65,41387.8) ; v1(48584.65,41879.92) C461.1@48584.65,41909.45 ; C464.1@48584.65,42460.63 v1(48584.65,42490.16) ; v1(48584.65,42982.28) C470.1@48584.65,43011.81 ; C477.1@48590.55,43562.99 v1(48590.55,43592.52) ; v1(48602.36,39675.2) C534.1@48602.36,39704.72 ; C536.1@48663.39,40255.91 v1(48663.39,40285.43) ; v1(48663.39,40777.56) C546.1@48663.39,40807.09 ; C456.1@48663.39,41358.27 v1(48663.39,41387.8) ; v1(48663.39,41879.92) C462.1@48663.39,41909.45 ; C463.1@48663.39,42460.63 v1(48663.39,42490.16) ; v1(48663.39,42982.28) C472.1@48663.39,43011.81 ; C476.1@48663.39,43562.99 v1(48663.39,43592.52) ; v1(48675.2,39675.2) C535.1@48675.2,39704.72 ; v1(48722.44,39675.2) C432.1@48722.44,39704.72 ; C498.1@48722.44,40255.91 v1(48722.44,40285.43) ; v1(48722.44,40777.56) C433.1@48722.44,40807.09 ; C497.1@48722.44,41358.27 v1(48722.44,41387.8) ; v1(48722.44,41879.92) C492.1@48722.44,41909.45 ; C496.1@48722.44,42460.63 v1(48722.44,42490.16) ; v1(48722.44,42982.28) C493.1@48722.44,43011.81 ; C438.1@48722.44,43562.99 v1(48722.44,43592.52) ; C583.2@48767.72,43748.03 v1(48832.68,43748.03) ; C583.2@48771.65,43787.4 v1(48832.68,43787.4) ; C541.1@48870.08,39891.73 v1(48899.61,39891.73) ; C540.1@48870.08,39970.47 v1(48899.61,39970.47) ; C539.1@48870.08,40049.21 v1(48899.61,40049.21) ; C547.1@48870.08,40994.09 v1(48899.61,40994.09) ; C471.1@48870.08,41072.83 v1(48899.61,41072.83) ; C440.1@48870.08,41151.57 v1(48899.61,41151.57) ; C466.1@48870.08,42096.46 v1(48899.61,42096.46) ; C467.1@48870.08,42175.2 v1(48899.61,42175.2) ; C468.1@48870.08,42253.94 v1(48899.61,42253.94) ; C473.1@48870.08,43198.82 v1(48899.61,43198.82) ; C474.1@48870.08,43277.56 v1(48899.61,43277.56) ; C475.1@48870.08,43356.3 v1(48899.61,43356.3)
  Bottom Layer w15: v1(40099,44295) R11.2@40123.47,44295 ; v1(42441.52,44295) R32.2@42465.99,44295 ; v1(44886.4,44295) R46.2@44910.87,44295 ; v1(47240.73,44295) R60.2@47265.2,44295
  other v1: 40910,40030 47025,43965 39675,43970 39880,43970 42220,43970 44670,43970
  other v2: 39889.76,39885.83 39937.01,39885.83 39984.25,39885.83 40031.5,39885.83 40078.74,39885.83 41118.11,39885.83 41165.35,39885.83 41212.6,39885.83 41259.84,39885.83 41307.09,39885.83 42350.39,39885.83 42397.64,39885.83 42444.88,39885.83 42492.13,39885.83 42539.37,39885.83 43578.74,39885.83 43625.98,39885.83 43673.23,39885.83 43720.47,39885.83 43767.72,39885.83 44811.02,39885.83 44858.27,39885.83 44905.51,39885.83 44952.76,39885.83 45000,39885.83 46039.37,39885.83 46086.61,39885.83 46133.86,39885.83 46181.1,39885.83 46228.35,39885.83 47271.65,39885.83 47318.9,39885.83 47366.14,39885.83 47413.39,39885.83 47460.63,39885.83 48500,39885.83 48547.24,39885.83 48594.49,39885.83 48641.73,39885.83 48688.98,39885.83 39889.76,39933.07 39937.01,39933.07 39984.25,39933.07 40078.74,39933.07 41118.11,39933.07 41165.35,39933.07 41212.6,39933.07 41259.84,39933.07 41307.09,39933.07 42350.39,39933.07 42397.64,39933.07 42444.88,39933.07 42492.13,39933.07 42539.37,39933.07 43578.74,39933.07 43625.98,39933.07 43673.23,39933.07 43720.47,39933.07 43767.72,39933.07 44811.02,39933.07 44858.27,39933.07 44905.51,39933.07 44952.76,39933.07 45000,39933.07 46039.37,39933.07 46086.61,39933.07 46133.86,39933.07 46181.1,39933.07 46228.35,39933.07 47271.65,39933.07 47318.9,39933.07 47366.14,39933.07 47413.39,39933.07 47460.63,39933.07 48500,39933.07 48547.24,39933.07 48594.49,39933.07 48641.73,39933.07 48688.98,39933.07 39889.76,39980.32 39937.01,39980.32 40031.5,39980.32 40078.74,39980.32 41118.11,39980.32 41165.35,39980.32 41212.6,39980.32 41259.84,39980.32 41307.09,39980.32 42350.39,39980.31 42397.64,39980.31 42444.88,39980.31 42492.13,39980.31 42539.37,39980.31 43578.74,39980.32 43625.98,39980.32 43673.23,39980.32 43720.47,39980.32 43767.72,39980.32 44811.02,39980.32 44858.27,39980.32 44905.51,39980.32 44952.76,39980.32 45000,39980.32 46039.37,39980.32 46086.61,39980.32 46133.86,39980.32 46181.1,39980.32 46228.35,39980.32 47271.65,39980.32 47318.9,39980.32 47366.14,39980.32 47413.39,39980.32 47460.63,39980.32 48500,39980.32 48547.24,39980.32 48594.49,39980.32 48641.73,39980.32 48688.98,39980.32 39889.76,40027.56 39937.01,40027.56 39984.25,40027.56 40031.5,40027.56 40078.74,40027.56 41118.11,40027.56 41165.35,40027.56 41212.6,40027.56 41259.84,40027.56 41307.09,40027.56 42350.39,40027.56 42397.64,40027.56 42444.88,40027.56 42492.13,40027.56 42539.37,40027.56 43578.74,40027.56 43625.98,40027.56 43673.23,40027.56 43720.47,40027.56 43767.72,40027.56 44811.02,40027.56 44858.27,40027.56 44905.51,40027.56 44952.76,40027.56 45000,40027.56 46039.37,40027.56 46086.61,40027.56 46133.86,40027.56 46181.1,40027.56 46228.35,40027.56 47271.65,40027.56 47318.9,40027.56 47366.14,40027.56 47413.39,40027.56 47460.63,40027.56 48500,40027.56 48547.24,40027.56 48594.49,40027.56 48641.73,40027.56 48688.98,40027.56 39889.76,40074.8 39937.01,40074.8 39984.25,40074.8 40031.5,40074.8 40078.74,40074.8 41118.11,40074.8 41165.35,40074.8 41212.6,40074.8 41259.84,40074.8 41307.09,40074.8 42350.39,40074.8 42397.64,40074.8 42444.88,40074.8 42492.13,40074.8 42539.37,40074.8 43578.74,40074.8 43625.98,40074.8 43673.23,40074.8 43720.47,40074.8 43767.72,40074.8 44811.02,40074.8 44858.27,40074.8 44905.51,40074.8 44952.76,40074.8 45000,40074.8 46039.37,40074.8 46086.61,40074.8 46133.86,40074.8 46181.1,40074.8 46228.35,40074.8 47271.65,40074.8 47318.9,40074.8 47366.14,40074.8 47413.39,40074.8 47460.63,40074.8 48500,40074.8 48547.24,40074.8 48594.49,40074.8 48641.73,40074.8 48688.98,40074.8 39889.76,40988.19 39937.01,40988.19 39984.25,40988.19 40031.5,40988.19 40078.74,40988.19 41118.11,40988.19 41165.35,40988.19 41212.6,40988.19 41259.84,40988.19 41307.09,40988.19 42350.39,40988.19 42397.64,40988.19 42444.88,40988.19 42492.13,40988.19 42539.37,40988.19 43578.74,40988.19 43625.98,40988.19 43673.23,40988.19 43720.47,40988.19 43767.72,40988.19 44811.02,40988.19 44858.27,40988.19 44905.51,40988.19 44952.76,40988.19 45000,40988.19 46039.37,40988.19 46086.61,40988.19 46133.86,40988.19 46181.1,40988.19 46228.35,40988.19 47271.65,40988.19 47318.9,40988.19 47366.14,40988.19 47413.39,40988.19 47460.63,40988.19 48500,40988.19 48547.24,40988.19 48594.49,40988.19 48641.73,40988.19 48688.98,40988.19 39889.76,41035.43 39937.01,41035.43 39984.25,41035.43 40031.5,41035.43 40078.74,41035.43 41118.11,41035.43 41165.35,41035.43 41212.6,41035.43 41259.84,41035.43 41307.09,41035.43 42350.39,41035.43 42397.64,41035.43 42444.88,41035.43 42492.13,41035.43 42539.37,41035.43 43578.74,41035.43 43625.98,41035.43 43673.23,41035.43 43720.47,41035.43 43767.72,41035.43 44811.02,41035.43 44858.27,41035.43 44905.51,41035.43 44952.76,41035.43 45000,41035.43 46039.37,41035.43 46086.61,41035.43 46133.86,41035.43 46181.1,41035.43 46228.35,41035.43 47271.65,41035.43 47318.9,41035.43 47366.14,41035.43 47413.39,41035.43 47460.63,41035.43 48500,41035.43 48547.24,41035.43 48594.49,41035.43 48641.73,41035.43 48688.98,41035.43 39889.76,41082.68 39937.01,41082.68 39984.25,41082.68 40031.5,41082.68 40078.74,41082.68 41118.11,41082.68 41165.35,41082.68 41212.6,41082.68 41259.84,41082.68 41307.09,41082.68 42350.39,41082.68 42397.64,41082.68 42444.88,41082.68 42492.13,41082.68 42539.37,41082.68 43578.74,41082.68 43625.98,41082.68 43673.23,41082.68 43720.47,41082.68 43767.72,41082.68 44811.02,41082.68 44858.27,41082.68 44905.51,41082.68 44952.76,41082.68 45000,41082.68 46039.37,41082.68 46086.61,41082.68 46133.86,41082.68 46181.1,41082.68 46228.35,41082.68 47271.65,41082.68 47318.9,41082.68 47366.14,41082.68 47413.39,41082.68 47460.63,41082.68 48500,41082.68 48547.24,41082.68 48594.49,41082.68 48641.73,41082.68 48688.98,41082.68 39889.76,41129.92 39937.01,41129.92 39984.25,41129.92 40031.5,41129.92 40078.74,41129.92 41118.11,41129.92 41165.35,41129.92 41212.6,41129.92 41259.84,41129.92 41307.09,41129.92 42350.39,41129.92 42397.64,41129.92 42444.88,41129.92 42492.13,41129.92 42539.37,41129.92 43578.74,41129.92 43625.98,41129.92 43673.23,41129.92 43720.47,41129.92 43767.72,41129.92 44811.02,41129.92 44858.27,41129.92 44905.51,41129.92 44952.76,41129.92 45000,41129.92 46039.37,41129.92 46086.61,41129.92 46133.86,41129.92 46181.1,41129.92 46228.35,41129.92 47271.65,41129.92 47318.9,41129.92 47366.14,41129.92 47413.39,41129.92 47460.63,41129.92 48500,41129.92 48547.24,41129.92 48594.49,41129.92 48641.73,41129.92 48688.98,41129.92 39889.76,41177.17 39937.01,41177.17 39984.25,41177.17 40031.5,41177.17 40078.74,41177.17 41118.11,41177.17 41165.35,41177.17 41212.6,41177.17 41259.84,41177.17 41307.09,41177.17 42350.39,41177.17 42397.64,41177.17 42444.88,41177.17 42492.13,41177.17 42539.37,41177.17 43578.74,41177.17 43625.98,41177.17 43673.23,41177.17 43720.47,41177.17 43767.72,41177.17 44811.02,41177.17 44858.27,41177.17 44905.51,41177.17 44952.76,41177.17 45000,41177.17 46039.37,41177.17 46086.61,41177.17 46133.86,41177.17 46181.1,41177.17 46228.35,41177.17 47271.65,41177.17 47318.9,41177.17 47366.14,41177.17 47413.39,41177.17 47460.63,41177.17 48500,41177.17 48547.24,41177.17 48594.49,41177.17 48641.73,41177.17 48688.98,41177.17 39889.76,42090.55 39937.01,42090.55 39984.25,42090.55 40031.5,42090.55 40078.74,42090.55 41118.11,42090.55 41165.35,42090.55 41212.6,42090.55 41259.84,42090.55 41307.09,42090.55 42350.39,42090.55 42397.64,42090.55 42444.88,42090.55 42492.13,42090.55 42539.37,42090.55 43578.74,42090.55 43625.98,42090.55 43673.23,42090.55 43720.47,42090.55 43767.72,42090.55 44811.02,42090.55 44858.27,42090.55 44905.51,42090.55 44952.76,42090.55 45000,42090.55 46039.37,42090.55 46086.61,42090.55 46133.86,42090.55 46181.1,42090.55 46228.35,42090.55 47271.65,42090.55 47318.9,42090.55 47366.14,42090.55 47413.39,42090.55 47460.63,42090.55 48500,42090.55 48547.24,42090.55 48594.49,42090.55 48641.73,42090.55 48688.98,42090.55 39889.76,42137.8 39937.01,42137.8 39984.25,42137.8 40031.5,42137.8 40078.74,42137.8 41118.11,42137.8 41165.35,42137.8 41212.6,42137.8 41259.84,42137.8 41307.09,42137.8 42350.39,42137.8 42397.64,42137.8 42444.88,42137.8 42492.13,42137.8 42539.37,42137.8 43578.74,42137.8 43625.98,42137.8 43673.23,42137.8 43720.47,42137.8 43767.72,42137.8 44811.02,42137.8 44858.27,42137.8 44905.51,42137.8 44952.76,42137.8 45000,42137.8 46039.37,42137.8 46086.61,42137.8 46133.86,42137.8 46181.1,42137.8 46228.35,42137.8 47271.65,42137.8 47318.9,42137.8 47366.14,42137.8 47413.39,42137.8 47460.63,42137.8 48500,42137.8 48547.24,42137.8 48594.49,42137.8 48641.73,42137.8 48688.98,42137.8 39889.76,42185.04 39937.01,42185.04 39984.25,42185.04 40031.5,42185.04 40078.74,42185.04 41118.11,42185.04 41165.35,42185.04 41212.6,42185.04 41259.84,42185.04 41307.09,42185.04 42350.39,42185.04 42397.64,42185.04 42444.88,42185.04 42492.13,42185.04 42539.37,42185.04 43578.74,42185.04 43625.98,42185.04 43673.23,42185.04 43720.47,42185.04 43767.72,42185.04 44811.02,42185.04 44858.27,42185.04 44905.51,42185.04 44952.76,42185.04 45000,42185.04 46039.37,42185.04 46086.61,42185.04 46133.86,42185.04 46181.1,42185.04 46228.35,42185.04 47271.65,42185.04 47318.9,42185.04 47366.14,42185.04 47413.39,42185.04 47460.63,42185.04 48500,42185.04 48547.24,42185.04 48594.49,42185.04 48641.73,42185.04 48688.98,42185.04 39889.76,42232.28 39937.01,42232.28 39984.25,42232.28 40031.5,42232.28 40078.74,42232.28 41118.11,42232.28 41165.35,42232.28 41212.6,42232.28 41259.84,42232.28 41307.09,42232.28 42350.39,42232.28 42397.64,42232.28 42444.88,42232.28 42492.13,42232.28 42539.37,42232.28 43578.74,42232.28 43625.98,42232.28 43673.23,42232.28 43720.47,42232.28 43767.72,42232.28 44811.02,42232.28 44858.27,42232.28 44905.51,42232.28 44952.76,42232.28 45000,42232.28 46039.37,42232.28 46086.61,42232.28 46133.86,42232.28 46181.1,42232.28 46228.35,42232.28 47271.65,42232.28 47318.9,42232.28 47366.14,42232.28 47413.39,42232.28 47460.63,42232.28 48500,42232.28 48547.24,42232.28 48594.49,42232.28 48641.73,42232.28 48688.98,42232.28 39889.76,42279.53 39937.01,42279.53 39984.25,42279.53 40031.5,42279.53 40078.74,42279.53 41118.11,42279.53 41165.35,42279.53 41212.6,42279.53 41259.84,42279.53 41307.09,42279.53 42350.39,42279.53 42397.64,42279.53 42444.88,42279.53 42492.13,42279.53 42539.37,42279.53 43578.74,42279.53 43625.98,42279.53 43673.23,42279.53 43720.47,42279.53 43767.72,42279.53 44811.02,42279.53 44858.27,42279.53 44905.51,42279.53 44952.76,42279.53 45000,42279.53 46039.37,42279.53 46086.61,42279.53 46133.86,42279.53 46181.1,42279.53 46228.35,42279.53 47271.65,42279.53 47318.9,42279.53 47366.14,42279.53 47413.39,42279.53 47460.63,42279.53 48500,42279.53 48547.24,42279.53 48594.49,42279.53 48641.73,42279.53 48688.98,42279.53 39937.01,43192.91 39984.25,43192.91 40031.5,43192.91 41165.35,43192.91 41212.6,43192.91 41259.84,43192.91 42350.39,43192.91 42397.64,43192.91 42444.88,43192.91 42492.13,43192.91 42539.37,43192.91 43578.74,43192.91 43625.98,43192.91 43673.23,43192.91 43720.47,43192.91 43767.72,43192.91 44811.02,43192.91 44858.27,43192.91 44905.51,43192.91 44952.76,43192.91 45000,43192.91 46039.37,43192.91 46086.61,43192.91 46133.86,43192.91 46181.1,43192.91 46228.35,43192.91 47271.65,43192.91 47318.9,43192.91 47366.14,43192.91 47413.39,43192.91 47460.63,43192.91 48500,43192.91 48547.24,43192.91 48594.49,43192.91 48641.73,43192.91 48688.98,43192.91 39889.76,43240.16 39984.25,43240.16 40078.74,43240.16 41118.11,43240.16 41212.6,43240.16 41307.09,43240.16 42350.39,43240.16 42397.64,43240.16 42444.88,43240.16 42492.13,43240.16 42539.37,43240.16 43578.74,43240.16 43625.98,43240.16 43673.23,43240.16 43720.47,43240.16 43767.72,43240.16 44811.02,43240.16 44858.27,43240.16 44905.51,43240.16 44952.76,43240.16 45000,43240.16 46039.37,43240.16 46086.61,43240.16 46133.86,43240.16 46181.1,43240.16 46228.35,43240.16 47271.65,43240.16 47318.9,43240.16 47366.14,43240.16 47413.39,43240.16 47460.63,43240.16 48500,43240.16 48547.24,43240.16 48594.49,43240.16 48641.73,43240.16 48688.98,43240.16 39889.76,43287.4 39937.01,43287.4 40031.5,43287.4 40078.74,43287.4 41118.11,43287.4 41165.35,43287.4 41212.6,43287.4 41259.84,43287.4 41307.09,43287.4 42350.39,43287.4 42397.64,43287.4 42444.88,43287.4 42492.13,43287.4 42539.37,43287.4 43578.74,43287.4 43625.98,43287.4 43673.23,43287.4 43720.47,43287.4 43767.72,43287.4 44811.02,43287.4 44858.27,43287.4 44905.51,43287.4 44952.76,43287.4 45000,43287.4 46039.37,43287.4 46086.61,43287.4 46133.86,43287.4 46181.1,43287.4 46228.35,43287.4 47271.65,43287.4 47318.9,43287.4 47366.14,43287.4 47413.39,43287.4 47460.63,43287.4 48500,43287.4 48547.24,43287.4 48641.73,43287.4 48688.98,43287.4 39889.76,43334.65 39984.25,43334.65 40078.74,43334.65 41118.11,43334.65 41165.35,43334.65 41212.6,43334.65 41259.84,43334.65 41307.09,43334.65 42350.39,43334.65 42397.64,43334.65 42444.88,43334.65 42492.13,43334.65 42539.37,43334.65 43578.74,43334.65 43625.98,43334.65 43673.23,43334.65 43720.47,43334.65 43767.72,43334.65 44811.02,43334.65 44858.27,43334.65 44905.51,43334.65 44952.76,43334.65 45000,43334.65 46039.37,43334.65 46086.61,43334.65 46133.86,43334.65 46181.1,43334.65 46228.35,43334.65 47271.65,43334.65 47318.9,43334.65 47366.14,43334.65 47413.39,43334.65 47460.63,43334.65 48500,43334.65 48594.49,43334.65 48641.73,43334.65 48688.98,43334.65 39937.01,43381.89 39984.25,43381.89 40031.5,43381.89 41118.11,43381.89 41165.35,43381.89 41212.6,43381.89 41259.84,43381.89 41307.09,43381.89 42350.39,43381.89 42397.64,43381.89 42444.88,43381.89 42492.13,43381.89 42539.37,43381.89 43578.74,43381.89 43625.98,43381.89 43673.23,43381.89 43720.47,43381.89 43767.72,43381.89 44811.02,43381.89 44858.27,43381.89 44905.51,43381.89 44952.76,43381.89 45000,43381.89 46039.37,43381.89 46086.61,43381.89 46133.86,43381.89 46181.1,43381.89 46228.35,43381.89 47271.65,43381.89 47318.9,43381.89 47366.14,43381.89 47413.39,43381.89 47460.63,43381.89 48547.24,43381.89 48594.49,43381.89 48641.73,43381.89 48688.98,43381.89
  other v3: 44375,44150 44420,44150 44330,44190 44375,44190 44420,44190 44330,44230 44375,44230 44420,44230 39440,44250 39480,44250 39520,44250 39560,44250 39600,44250 49070,44270 49115,44270 49160,44270 48330,44275 48375,44275 48420,44275 48515,44275 48560,44275 48605,44275 48785,44275 48830,44275 48875,44275 39440,44280 39480,44280 39520,44280 39560,44280 39600,44280 45985,44290 46030,44290 46075,44290 46165,44290 46210,44290 46255,44290 46655,44290 46700,44290 46745,44290 43545,44295 43590,44295 43635,44295 43720,44295 43765,44295 43810,44295 43980,44295 44025,44295 44070,44295 46420,44295 46465,44295 46510,44295 44330,44305 44375,44305 44420,44305 49070,44310 49115,44310 49160,44310 48330,44315 48375,44315 48420,44315 48515,44315 48560,44315 48605,44315 48785,44315 48830,44315 48875,44315 41645,44325 41690,44325 41735,44325 45985,44330 46030,44330 46075,44330 46165,44330 46210,44330 46255,44330 46655,44330 46700,44330 46745,44330 43545,44335 43590,44335 43635,44335 43720,44335 43765,44335 43810,44335 43980,44335 44025,44335 44070,44335 46420,44335 46465,44335 46510,44335 44330,44345 44375,44345 44420,44345 41200,44350 41245,44350 41290,44350 41335,44350 41380,44350 41425,44350 41470,44350 49070,44350 49115,44350 49160,44350 48330,44355 48375,44355 48420,44355 48515,44355 48560,44355 48605,44355 48785,44355 48830,44355 48875,44355 41645,44365 41690,44365 41735,44365 45985,44370 46030,44370 46075,44370 46165,44370 46210,44370 46255,44370 46655,44370 46700,44370 46745,44370 43545,44375 43590,44375 43635,44375 43720,44375 43765,44375 43810,44375 43980,44375 44025,44375 44070,44375 46420,44375 46465,44375 46510,44375 44330,44385 44375,44385 44420,44385 41200,44390 41245,44390 41290,44390 41335,44390 41380,44390 41425,44390 41470,44390 41645,44405 41690,44405 41735,44405 48080,44410 48125,44410 48170,44410 48330,44410 48375,44410 48420,44410 48515,44410 48560,44410 48605,44410 48785,44415 48830,44415 48875,44415 39440,44420 39480,44420 39520,44420 39560,44420 39600,44420 40925,44430 40970,44430 41015,44430 41200,44430 41245,44430 41290,44430 41335,44430 41380,44430 41425,44430 41470,44430 45985,44430 46030,44430 46075,44430 46165,44430 46210,44430 46255,44430 43260,44435 43305,44435 43350,44435 43545,44435 43590,44435 43635,44435 43720,44435 43765,44435 43810,44435 46420,44435 46465,44435 46510,44435 43980,44440 44025,44440 44070,44440 41645,44445 41690,44445 41735,44445 39440,44450 39480,44450 39520,44450 39560,44450 39600,44450 48080,44450 48125,44450 48170,44450 48330,44450 48375,44450 48420,44450 48515,44450 48560,44450 48605,44450 48785,44455 48830,44455 48875,44455 40500,44465 40545,44465 40590,44465 47225,44465 47270,44465 47315,44465 40925,44470 40970,44470 41015,44470 41200,44470 41245,44470 41290,44470 41335,44470 41380,44470 41425,44470 41470,44470 42840,44470 42885,44470 42930,44470 45735,44470 45780,44470 45825,44470 45985,44470 46030,44470 46075,44470 46165,44470 46210,44470 46255,44470 40035,44475 40080,44475 40125,44475 43260,44475 43305,44475 43350,44475 43545,44475 43590,44475 43635,44475 43720,44475 43765,44475 43810,44475 45280,44475 45325,44475 45370,44475 46420,44475 46465,44475 46510,44475 43980,44480 44025,44480 44070,44480 41645,44485 41690,44485 41735,44485 44820,44485 44865,44485 44910,44485 48080,44490 48125,44490 48170,44490 48330,44490 48375,44490 48420,44490 48515,44490 48560,44490 48605,44490 48785,44495 48830,44495 48875,44495 40500,44505 40545,44505 40590,44505 47225,44505 47270,44505 47315,44505 40925,44510 40970,44510 41015,44510 41200,44510 41245,44510 41290,44510 41335,44510 41380,44510 41425,44510 41470,44510 42840,44510 42885,44510 42930,44510 45735,44510 45780,44510 45825,44510 45985,44510 46030,44510 46075,44510 46165,44510 46210,44510 46255,44510 40080,44515 40125,44515 43260,44515 43305,44515 43350,44515 43545,44515 43590,44515 43635,44515 43720,44515 43765,44515 43810,44515 45280,44515 45325,44515 45370,44515 46420,44515 46465,44515 46510,44515 43980,44520 44025,44520 44070,44520 44865,44525 44910,44525 40500,44545 40545,44545 40590,44545 47225,44545 47270,44545 47315,44545 42840,44550 42885,44550 42930,44550 45735,44550 45780,44550 45825,44550 40125,44555 45280,44555 45325,44555 45370,44555 44910,44565 48820,44715 48865,44715 48910,44715 47225,44720 47270,44720 47315,44720 48820,44755 48865,44755 48910,44755 47225,44760 47270,44760 47315,44760 48820,44795 48865,44795 48910,44795 47225,44800 47270,44800 47315,44800 42695,44900 42335,44905 41965,44975 42300,44975 43520,45040 43570,45040 43620,45040 43670,45040 43720,45040 43770,45040 43820,45040 43870,45040 43920,45040 43970,45040 44020,45040 44070,45040 40065,45080 43520,45085 43670,45085 43720,45085 43870,45085 43920,45085 44070,45090 41160,45110 43520,45130 43670,45130 43720,45130 43870,45130 43920,45130 44070,45130 47205,45130 47250,45130 47295,45130 41965,45140 42405,45145 42455,45145 42380,45170 42430,45170 47205,45170 47250,45170 47295,45170 43520,45175 43570,45175 43620,45175 43670,45175 43720,45175 43770,45175 43820,45175 43870,45175 43920,45175 43970,45175 44020,45175 44070,45175 42405,45195 42455,45195 47205,45210 47250,45210 47295,45210 42690,45220 43520,45220 43570,45220 43620,45220 43670,45220 43720,45220 43770,45220 43820,45220 43870,45220 43920,45220 43970,45220 44020,45220 44070,45220 41160,45225 41660,45225 41755,45225 42310,45230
